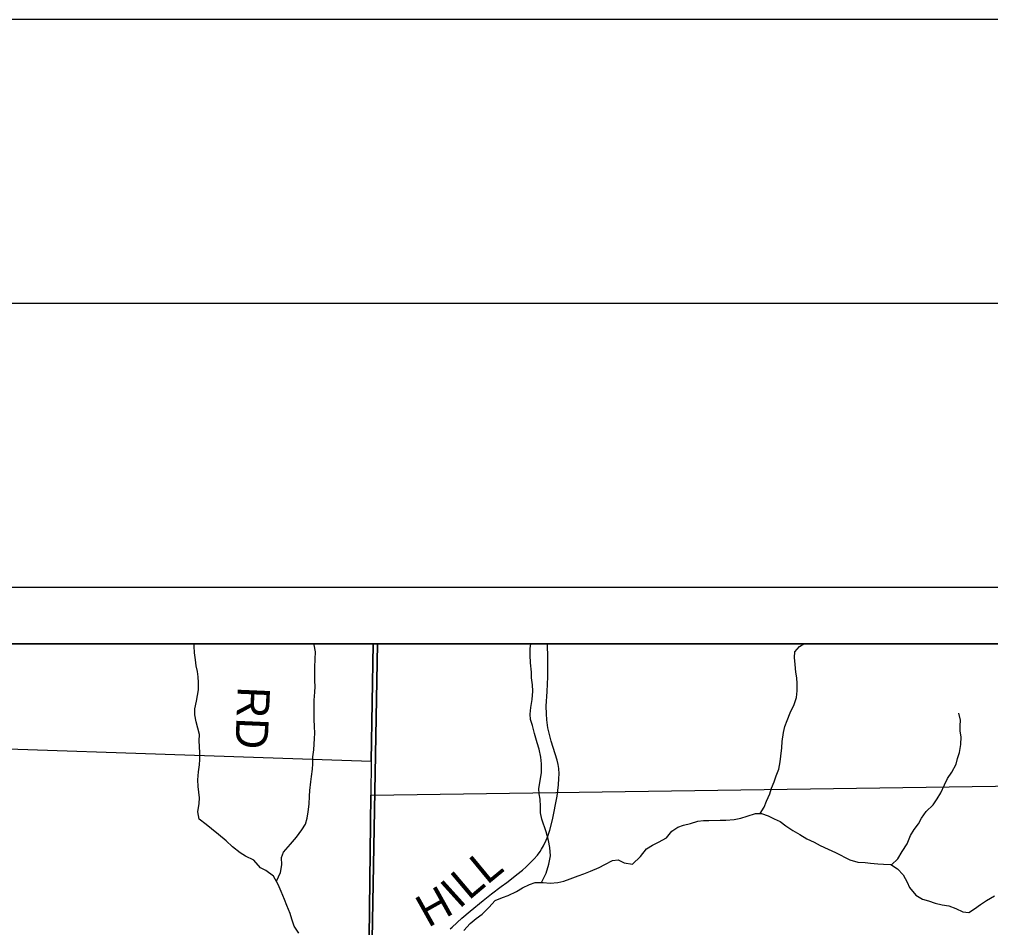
# Model space of a CAD drawing. Extents: x 0 to 34, y 0 to 22.
# Drawn here: x 3.957 to 5.667, y 20.4 to 22 of the extents above; entities that cross this region are included whole.
import ezdxf

# ---------------------------------------------------------------- set-up
doc = ezdxf.new("R2010")
doc.units = 0
for name, color, linetype in [('Default', 7, 'Continuous'), ('GM_X_County_Road', 7, 'Continuous'), ('GM_X_County_Road_Text', 7, 'Continuous'), ('GM_X_Minor_River', 7, 'Continuous'), ('GM_X_Rail_Line', 7, 'Continuous'), ('GM_X_Section', 7, 'Continuous'), ('GM_X_Township_Road_Text', 7, 'Continuous'), ('SH_Border', 7, 'Continuous'), ('SH_Cut_Line', 7, 'Continuous'), ('SH_Data', 7, 'Continuous')]:
    doc.layers.add(name, color=color, linetype=linetype)

msp = doc.modelspace()

# ---------------------------------------------------------------- linework, layer by layer
at = {"layer": 'Default'}
for points in [[(4.5799, 20.9), (3.5777, 20.9), (3.5738, 20.7275), (4.5766, 20.6934)], [(5.7998, 20.9), (4.5799, 20.9), (4.5766, 20.6934), (4.5761, 20.6339), (5.7984, 20.651)]]:
    msp.add_lwpolyline(points, close=True, dxfattribs=at)
at = {"layer": 'GM_X_County_Road'}
msp.add_lwpolyline([(4.7154, 20.3981), (4.7189, 20.4011), (4.7364, 20.4168), (4.7506, 20.4292), (4.7737, 20.4483), (4.7883, 20.4597), (4.8057, 20.473), (4.8154, 20.4801), (4.8266, 20.4886), (4.8333, 20.4937), (4.8433, 20.5016), (4.8496, 20.5075), (4.8547, 20.5125), (4.8633, 20.5212), (4.8692, 20.528), (4.874, 20.5342), (4.8767, 20.5383), (4.8803, 20.5443), (4.8847, 20.5545), (4.8878, 20.5616), (4.8914, 20.5722), (4.8961, 20.59), (4.9042, 20.6318), (4.9062, 20.6516), (4.9073, 20.6628), (4.9077, 20.671), (4.907, 20.6804), (4.9058, 20.6877), (4.9039, 20.6953), (4.8933, 20.729), (4.8879, 20.7523), (4.886, 20.7666), (4.8852, 20.7772), (4.8847, 20.7905), (4.8866, 20.816), (4.8875, 20.8422), (4.8874, 20.875), (4.8872, 20.9)], dxfattribs=at)
at = {"layer": 'GM_X_Minor_River'}
for points in [[(4.449, 20.3906), (4.4409, 20.4031), (4.437, 20.4152), (4.4339, 20.4254), (4.4278, 20.4394), (4.4239, 20.45), (4.4177, 20.464), (4.4127, 20.4765), (4.4046, 20.4909), (4.3909, 20.5007), (4.3814, 20.5059), (4.3699, 20.5191), (4.3554, 20.5263), (4.3455, 20.5323), (4.3325, 20.5424), (4.3211, 20.553), (4.3077, 20.5643), (4.2955, 20.5744), (4.2859, 20.582), (4.2737, 20.5914), (4.2714, 20.6043), (4.2736, 20.6187), (4.2743, 20.6289), (4.273, 20.6388), (4.2715, 20.6487), (4.271, 20.6604), (4.2724, 20.6749), (4.2742, 20.687), (4.2746, 20.6965), (4.2745, 20.709), (4.2736, 20.7295), (4.2739, 20.7405), (4.2712, 20.7515), (4.2681, 20.7629), (4.2661, 20.775), (4.266, 20.786), (4.2686, 20.7993), (4.2704, 20.8092), (4.2722, 20.8194), (4.2722, 20.832), (4.2717, 20.8418), (4.2705, 20.8517), (4.2685, 20.8612), (4.2673, 20.8718), (4.2654, 20.8843), (4.2645, 20.896), (4.2645, 20.9)], [(4.4095, 20.4823), (4.4167, 20.4974), (4.4189, 20.5107), (4.4188, 20.5236), (4.4218, 20.5331), (4.4346, 20.5476), (4.4448, 20.5599), (4.4542, 20.5724), (4.4606, 20.5827), (4.4636, 20.5934), (4.4658, 20.6044), (4.4672, 20.6181), (4.4679, 20.6317), (4.4686, 20.6416), (4.47, 20.6572), (4.4714, 20.6667), (4.4729, 20.6792), (4.4736, 20.6887), (4.4739, 20.7012), (4.4753, 20.7137), (4.476, 20.7232), (4.4767, 20.7335), (4.477, 20.743), (4.4769, 20.7547), (4.4761, 20.7669), (4.476, 20.7885), (4.4763, 20.801), (4.4773, 20.8151), (4.4776, 20.8249), (4.4775, 20.8348), (4.4771, 20.8481), (4.477, 20.8591), (4.4777, 20.8731), (4.4784, 20.8864), (4.476, 20.8986), (4.4756, 20.9)], [(4.8766, 20.4796), (4.8849, 20.4963), (4.8897, 20.5123), (4.8923, 20.5267), (4.8914, 20.5415), (4.8887, 20.5536), (4.8848, 20.5688), (4.8771, 20.5911), (4.8747, 20.6025), (4.8746, 20.6139), (4.8742, 20.6264), (4.8726, 20.6363), (4.8718, 20.6457), (4.874, 20.6587), (4.8765, 20.6735), (4.8764, 20.6887), (4.8752, 20.7008), (4.8725, 20.7144), (4.8686, 20.7258), (4.8643, 20.7421), (4.8604, 20.7561), (4.8569, 20.7671), (4.8565, 20.7766), (4.8576, 20.788), (4.8601, 20.802), (4.8615, 20.8168), (4.8607, 20.8282), (4.8591, 20.8403), (4.8587, 20.8502), (4.8574, 20.8669), (4.8566, 20.8802), (4.8565, 20.8919), (4.8576, 20.9)], [(5.2616, 20.6015), (5.2688, 20.6127), (5.2729, 20.6233), (5.2785, 20.6359), (5.2815, 20.6458), (5.2863, 20.6572), (5.2901, 20.6678), (5.2945, 20.6792), (5.2971, 20.6922), (5.2982, 20.7024), (5.2996, 20.7172), (5.3007, 20.7282), (5.3028, 20.7438), (5.3051, 20.7544), (5.3092, 20.7651), (5.3144, 20.7788), (5.3215, 20.7936), (5.3256, 20.8054), (5.3267, 20.8176), (5.327, 20.8305), (5.3261, 20.8403), (5.3245, 20.8506), (5.3233, 20.8638), (5.3221, 20.876), (5.3228, 20.8862), (5.3307, 20.8958), (5.3385, 20.9)], [(5.4927, 20.511), (5.504, 20.5216), (5.5115, 20.5346), (5.5206, 20.5479), (5.5265, 20.5624), (5.5329, 20.573), (5.5405, 20.5833), (5.5457, 20.5932), (5.554, 20.605), (5.5661, 20.6165), (5.5732, 20.6272), (5.5796, 20.6375), (5.5863, 20.6519), (5.5916, 20.6633), (5.5991, 20.6744), (5.607, 20.6881), (5.6092, 20.6984), (5.6125, 20.709), (5.6151, 20.7227), (5.6158, 20.7364), (5.6142, 20.7462), (5.6141, 20.7557), (5.6144, 20.7659), (5.6113, 20.7781)], [(4.7398, 20.3952), (4.7511, 20.4078), (4.7617, 20.4162), (4.7722, 20.4239), (4.7839, 20.4361), (4.7949, 20.4483), (4.8081, 20.4537), (4.8176, 20.4568), (4.8327, 20.4637), (4.8429, 20.4702), (4.8554, 20.4764), (4.8653, 20.4799), (4.8793, 20.4796), (4.8915, 20.4785), (4.9055, 20.4798), (4.9158, 20.4821), (4.9271, 20.4863), (4.9411, 20.4914), (4.951, 20.4952), (4.9631, 20.4999), (4.9783, 20.506), (4.9881, 20.5118), (5.0017, 20.5187), (5.0116, 20.5195), (5.0222, 20.5147), (5.0367, 20.5121), (5.051, 20.5259), (5.0612, 20.5392), (5.0722, 20.5457), (5.0828, 20.5507), (5.0964, 20.5588), (5.1058, 20.5702), (5.1168, 20.5771), (5.1266, 20.5806), (5.1387, 20.5837), (5.1516, 20.588), (5.1619, 20.5892), (5.1713, 20.5893), (5.1911, 20.5898), (5.201, 20.5898), (5.2158, 20.5907), (5.2275, 20.593), (5.2389, 20.5965), (5.2537, 20.6012), (5.2639, 20.6016), (5.2757, 20.5972), (5.2864, 20.5919), (5.2967, 20.587), (5.3066, 20.5799), (5.3192, 20.5716), (5.3314, 20.5641), (5.3439, 20.5566), (5.3565, 20.551), (5.3676, 20.545), (5.3817, 20.5383), (5.3942, 20.5327), (5.4194, 20.5199), (5.4334, 20.5158), (5.4464, 20.5152), (5.4559, 20.5141), (5.4688, 20.5127), (5.4786, 20.5123), (5.4916, 20.5117), (5.5038, 20.5042), (5.5137, 20.4936), (5.5206, 20.4807), (5.5249, 20.4709), (5.5356, 20.4573), (5.5478, 20.4506), (5.5581, 20.4476), (5.5698, 20.4435), (5.582, 20.4405), (5.5938, 20.4387), (5.6064, 20.4339), (5.6189, 20.4283), (5.6292, 20.4272), (5.6394, 20.4333), (5.6496, 20.441), (5.6602, 20.4483), (5.6742, 20.4563)]]:
    msp.add_lwpolyline(points, dxfattribs=at)
at = {"layer": 'GM_X_Rail_Line'}
msp.add_lwpolyline([(4.5874, 20.9), (2.1, 20.9), (2.1, 18.7171), (2.7864, 18.6994), (2.7892, 18.6993), (2.9222, 18.6946), (2.9234, 18.6945), (3.8442, 18.6615), (3.8456, 18.6615), (4.5462, 18.6416), (4.5515, 18.7621), (4.5519, 18.771), (4.5566, 18.8683), (4.5569, 18.8737), (4.5569, 18.8748), (4.5571, 18.8875), (4.5772, 20.3136), (4.5773, 20.3149)], close=True, dxfattribs=at)
msp.add_lwpolyline([(8.8193, 20.9), (4.5874, 20.9), (4.5773, 20.3149), (4.5772, 20.3136), (4.5571, 18.8875), (4.5569, 18.8748), (4.5569, 18.8737), (4.5566, 18.8683), (4.5519, 18.771), (4.5515, 18.7621), (4.5462, 18.6416), (4.7887, 18.6396), (4.7954, 18.6396), (4.8076, 18.6387), (4.8445, 18.636), (4.8458, 18.6359), (5.4171, 18.6266), (7.3845, 18.6186)], dxfattribs=at)
at = {"layer": 'GM_X_Section'}
for points in [[(4.5766, 20.6934), (4.5761, 20.6339), (4.5646, 19.6808), (3.5637, 19.7201), (3.5738, 20.7275)], [(4.5761, 20.6339), (5.7984, 20.651), (5.7918, 19.6342), (4.5644, 19.6379), (4.5646, 19.6808)]]:
    msp.add_lwpolyline(points, close=True, dxfattribs=at)
at = {"layer": 'SH_Border'}
msp.add_lwpolyline([(1.5, 21.5), (33.5, 21.5), (33.5, 0.5), (1.5, 0.5)], close=True, dxfattribs=at)
at = {"layer": 'SH_Cut_Line'}
msp.add_lwpolyline([(0, 0), (34, 0), (34, 22), (0, 22)], close=True, dxfattribs=at)
msp.add_lwpolyline([(8.9, 14.624), (8.9, 20.9), (2.1, 20.9), (2.1, 14.1)], dxfattribs=at)
at = {"layer": 'SH_Data'}
for p, q in [((2, 21), (9, 21)), ((2.1, 20.9), (8.9, 20.9))]:
    msp.add_line(p, q, dxfattribs=at)

# ---------------------------------------------------------------- texts
at = {"layer": 'GM_X_County_Road_Text'}
for s, rotation, p in [('L', 39.5828, (4.7808, 20.4748)), ('L', 40.1973, (4.7485, 20.4474)), ('I', 42.0885, (4.7316, 20.4321)), ('H', 29.2067, (4.6768, 20.3997))]:
    msp.add_text(s, height=0.0568, rotation=rotation, dxfattribs=at).set_placement(p)
at = {"layer": 'GM_X_Township_Road_Text'}
msp.add_text('RD', height=0.05682, rotation=267.5314, dxfattribs=at).set_placement((4.3418, 20.8257))

doc.saveas('drawing.dxf')
